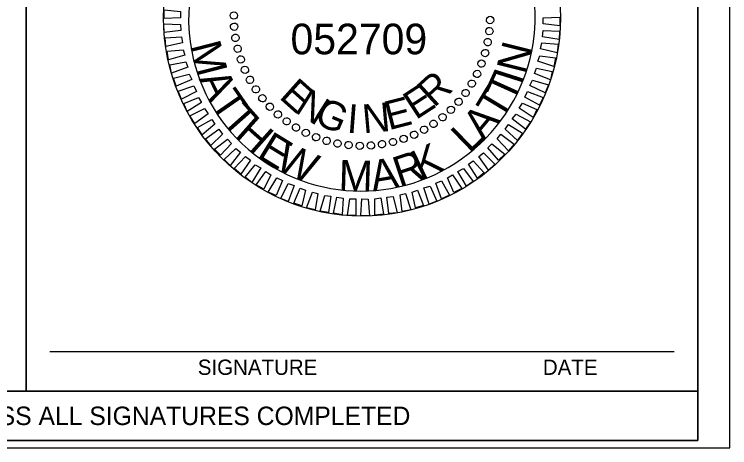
# Model space of a CAD drawing. Extents: x 265553 to 275568, y 168312 to 173522.
# Drawn here: x 273933.1 to 274213.2, y 172139.7 to 172309.6 of the extents above; entities that cross this region are included whole.
import ezdxf

# ---------------------------------------------------------------- set-up
doc = ezdxf.new("R2010")
doc.units = 0
for name, color, linetype in [('Geotech Sheets and Borders Cell', 7, 'Continuous'), ('Scratch_Level_0', 7, 'Continuous'), ('Scratch_Level_6', 7, 'Continuous'), ('Sheet Plot Border Inside CELL', 7, 'Continuous'), ('Sheet Professional Seal CELL', 7, 'Continuous'), ('Sheet Sticker Exception Certification CELL', 7, 'Continuous')]:
    doc.layers.add(name, color=color, linetype=linetype)

msp = doc.modelspace()

# ---------------------------------------------------------------- linework, layer by layer
at = {"layer": 'Geotech Sheets and Borders Cell'}
msp.add_line((274191.42, 172177.29), (273947, 172177.29), dxfattribs=at)
for points in [[(272700.69, 173192.58), (274200.69, 173192.58), (274200.69, 172142.58), (272700.69, 172142.58)], [(273674.76, 172409.27), (273937.73, 172409.27), (273937.73, 172161.9), (273674.76, 172161.9)], [(273937.73, 172409.27), (274200.69, 172409.27), (274200.69, 172161.9), (273937.73, 172161.9)]]:
    msp.add_lwpolyline(points, close=True, dxfattribs=at)
msp.add_lwpolyline([(274200.69, 172409.27), (273674.76, 172409.27), (273674.76, 172142.58), (274200.69, 172142.58), (274200.69, 172410.73)], dxfattribs=at)
at = {"layer": 'Scratch_Level_0'}
msp.add_ellipse((274069.21, 172308.22), major_axis=(45.09, 51.04), ratio=0.993455, start_param=1.731198, end_param=5.992706, dxfattribs=at)
at = {"layer": 'Scratch_Level_6'}
msp.add_circle((274069.21, 172308.22), 77.7, dxfattribs=at)
at = {"layer": 'Sheet Plot Border Inside CELL'}
msp.add_lwpolyline([(272545.53, 172139.74), (274213.19, 172139.74), (274213.19, 173195.41), (272545.53, 173195.41)], close=True, dxfattribs=at)
at = {"layer": 'Sheet Professional Seal CELL'}
for p, q in [((274019.01, 172309.12), (274019.01, 172309.12)), ((274119.41, 172307.32), (274119.41, 172307.32)), ((274019.11, 172304.72), (274019.11, 172304.72)), ((274119.11, 172302.92), (274119.11, 172302.92)), ((274019.71, 172300.42), (274019.71, 172300.42)), ((274118.41, 172298.62), (274118.41, 172298.62)), ((274020.51, 172296.02), (274020.51, 172296.02)), ((274117.51, 172294.42), (274117.51, 172294.42)), ((274021.71, 172291.82), (274021.71, 172291.82)), ((274116.11, 172290.22), (274116.11, 172290.22)), ((274023.31, 172287.82), (274023.31, 172287.82)), ((274114.31, 172286.22), (274114.31, 172286.22)), ((274025.31, 172283.92), (274025.31, 172283.92)), ((274112.31, 172282.32), (274112.31, 172282.32)), ((274027.61, 172280.12), (274027.61, 172280.12)), ((274109.81, 172278.72), (274109.81, 172278.72)), ((274030.11, 172276.62), (274030.11, 172276.62)), ((274107.11, 172275.22), (274107.11, 172275.22)), ((274033.11, 172273.32), (274033.11, 172273.32)), ((274104.11, 172272.12), (274104.11, 172272.12)), ((274036.21, 172270.32), (274036.21, 172270.32)), ((274039.71, 172267.62), (274039.71, 172267.62)), ((274097.31, 172266.62), (274097.31, 172266.62)), ((274100.81, 172269.12), (274100.81, 172269.12)), ((274043.31, 172265.12), (274043.31, 172265.12)), ((274093.51, 172264.32), (274093.51, 172264.32)), ((274047.21, 172263.12), (274047.21, 172263.12)), ((274051.21, 172261.32), (274051.21, 172261.32)), ((274089.61, 172262.32), (274089.61, 172262.32)), ((274055.41, 172259.92), (274055.41, 172259.92)), ((274059.61, 172259.02), (274059.61, 172259.02)), ((274063.91, 172258.32), (274063.91, 172258.32)), ((274068.31, 172258.02), (274068.31, 172258.02)), ((274072.71, 172258.12), (274072.71, 172258.12)), ((274077.01, 172258.72), (274077.01, 172258.72)), ((274081.41, 172259.52), (274081.41, 172259.52)), ((274085.61, 172260.72), (274085.61, 172260.72))]:
    msp.add_line(p, q, dxfattribs=at)
for points in [[(273998.21, 172308.22), (273991.71, 172307.92), (273991.71, 172311.32), (273998.21, 172310.62)], [(274140.21, 172308.22), (274146.71, 172308.52), (274146.71, 172305.12), (274140.21, 172305.82)], [(273998.31, 172303.22), (273991.81, 172302.42), (273991.61, 172305.82), (273998.11, 172305.62)], [(274140.11, 172303.22), (274146.61, 172303.02), (274146.41, 172299.72), (274139.91, 172300.82)], [(273998.91, 172298.42), (273992.41, 172297.02), (273992.11, 172300.42), (273998.51, 172300.82)], [(274139.61, 172298.42), (274146.01, 172297.82), (274145.61, 172294.42), (274139.11, 172296.02)], [(273999.81, 172293.62), (273993.51, 172291.72), (273992.91, 172295.12), (273999.21, 172295.72)], [(274138.81, 172293.32), (274145.01, 172292.52), (274144.31, 172289.12), (274138.01, 172291.22)], [(274001.01, 172288.82), (273994.61, 172286.52), (273994.01, 172289.82), (274000.31, 172290.92)], [(274002.61, 172284.02), (273996.51, 172281.42), (273995.41, 172284.52), (274001.61, 172286.12)], [(274137.51, 172288.52), (274143.71, 172287.22), (274143.01, 172283.92), (274136.71, 172286.42)], [(274136.01, 172283.72), (274142.21, 172281.92), (274140.91, 172278.82), (274134.91, 172281.62)], [(274004.41, 172279.32), (273998.51, 172276.32), (273997.21, 172279.52), (274003.41, 172281.52)], [(274134.01, 172279.32), (274140.21, 172277.02), (274138.71, 172273.92), (274133.01, 172277.12)], [(274006.41, 172275.02), (274000.81, 172271.52), (273999.51, 172274.62), (274005.21, 172276.92)], [(274009.01, 172270.62), (274003.71, 172266.82), (274001.81, 172269.82), (274007.61, 172272.62)], [(274132.01, 172274.72), (274137.71, 172272.22), (274136.21, 172269.12), (274130.81, 172272.82)], [(274129.61, 172270.42), (274135.21, 172267.42), (274133.21, 172264.62), (274128.01, 172268.62)], [(274011.61, 172266.52), (274006.71, 172262.32), (274004.81, 172265.22), (274010.41, 172268.42)], [(274126.61, 172266.42), (274132.01, 172263.02), (274130.11, 172260.12), (274125.31, 172264.52)], [(274014.61, 172262.62), (274010.01, 172258.12), (274007.91, 172260.82), (274013.21, 172264.62)], [(274123.61, 172262.62), (274128.81, 172258.72), (274126.61, 172256.12), (274122.21, 172260.82)], [(274018.11, 172259.02), (274013.81, 172254.32), (274011.41, 172256.72), (274016.61, 172260.62)], [(274120.11, 172258.82), (274125.21, 172254.72), (274122.71, 172252.42), (274118.51, 172257.22)], [(274021.71, 172255.52), (274017.61, 172250.32), (274015.21, 172252.72), (274019.81, 172257.02)], [(274116.81, 172255.32), (274121.21, 172250.92), (274118.81, 172248.52), (274114.91, 172253.92)], [(274025.51, 172252.42), (274021.81, 172246.92), (274019.21, 172249.12), (274023.61, 172253.82)], [(274029.61, 172249.42), (274026.11, 172243.62), (274023.51, 172245.72), (274027.41, 172250.62)], [(274112.81, 172252.22), (274117.11, 172247.42), (274114.41, 172245.32), (274110.91, 172250.92)], [(274033.51, 172246.72), (274030.81, 172241.02), (274027.81, 172242.72), (274031.61, 172247.92)], [(274109.01, 172249.22), (274112.71, 172244.12), (274110.11, 172242.22), (274106.81, 172248.02)], [(274038.11, 172244.42), (274035.61, 172238.52), (274032.51, 172239.92), (274035.91, 172245.52)], [(274100.31, 172244.32), (274103.51, 172238.72), (274100.41, 172237.32), (274098.11, 172243.42)], [(274104.61, 172246.72), (274108.31, 172241.32), (274105.21, 172239.72), (274102.71, 172245.52)], [(274042.61, 172242.52), (274040.31, 172236.22), (274037.51, 172237.42), (274040.31, 172243.22)], [(274047.11, 172240.72), (274045.61, 172234.52), (274042.51, 172235.52), (274045.01, 172241.42)], [(274095.91, 172242.22), (274098.51, 172236.42), (274095.51, 172235.22), (274093.41, 172241.62)], [(274051.91, 172239.42), (274050.91, 172232.92), (274047.51, 172233.72), (274049.81, 172239.92)], [(274057.01, 172238.32), (274056.11, 172231.92), (274052.81, 172232.42), (274054.61, 172238.62)], [(274086.21, 172239.32), (274088.31, 172233.02), (274084.91, 172232.32), (274084.11, 172238.82)], [(274091.01, 172240.62), (274093.31, 172234.62), (274090.21, 172233.72), (274088.91, 172239.92)], [(274061.81, 172237.52), (274061.41, 172231.02), (274058.11, 172231.62), (274059.41, 172237.92)], [(274066.81, 172237.22), (274066.81, 172230.72), (274063.51, 172230.82), (274064.41, 172237.32)], [(274071.61, 172237.12), (274072.11, 172230.62), (274068.81, 172230.72), (274069.21, 172237.22)], [(274076.61, 172237.62), (274077.71, 172231.22), (274074.31, 172230.82), (274074.21, 172237.32)], [(274081.41, 172238.22), (274083.01, 172231.82), (274079.71, 172231.52), (274079.01, 172237.92)]]:
    msp.add_lwpolyline(points, close=True, dxfattribs=at)
for centre, major_axis in [((274019.06, 172309.1), (-1.44, 0.03)), ((274119.36, 172307.35), (1.44, -0.03)), ((274019.17, 172304.72), (-1.44, -0.1)), ((274119.1, 172302.98), (1.43, -0.15)), ((274019.67, 172300.38), (-1.42, -0.23)), ((274118.45, 172298.65), (1.41, -0.27)), ((274020.54, 172296.09), (-1.4, -0.35)), ((274117.43, 172294.4), (1.38, -0.4)), ((274021.78, 172291.89), (-1.36, -0.47)), ((274116.04, 172290.25), (1.34, -0.52)), ((274023.39, 172287.82), (-1.32, -0.59)), ((274114.29, 172286.23), (1.29, -0.63)), ((274025.34, 172283.9), (-1.26, -0.7)), ((274112.21, 172282.39), (1.23, -0.74)), ((274027.63, 172280.17), (-1.19, -0.81)), ((274109.79, 172278.74), (1.16, -0.85)), ((274030.23, 172276.66), (-1.12, -0.91)), ((274033.13, 172273.38), (-1.04, -1)), ((274107.07, 172275.31), (1.09, -0.94)), ((274036.3, 172270.37), (-0.94, -1.09)), ((274104.05, 172272.14), (1, -1.04)), ((274039.73, 172267.64), (-0.85, -1.16)), ((274100.78, 172269.24), (0.91, -1.12)), ((274043.38, 172265.23), (-0.74, -1.23)), ((274097.26, 172266.64), (0.81, -1.19)), ((274047.22, 172263.14), (-0.63, -1.29)), ((274089.61, 172262.4), (0.59, -1.32)), ((274093.53, 172264.35), (0.7, -1.26)), ((274051.23, 172261.39), (-0.52, -1.34)), ((274055.38, 172260), (-0.4, -1.38)), ((274081.35, 172259.55), (0.35, -1.4)), ((274085.54, 172260.79), (0.47, -1.36)), ((274059.64, 172258.98), (-0.27, -1.41)), ((274063.97, 172258.34), (-0.15, -1.43)), ((274068.34, 172258.07), (-0.03, -1.44)), ((274072.71, 172258.18), (0.1, -1.44)), ((274077.06, 172258.68), (0.23, -1.42))]:
    msp.add_ellipse(centre, major_axis=major_axis, ratio=0.999708, dxfattribs=at)
at = {"layer": 'Sheet Sticker Exception Certification CELL'}
for p, q in [((273674.76, 172161.9), (274200.69, 172161.9)), ((274200.69, 172161.9), (274200.69, 172142.58)), ((273674.76, 172142.58), (274200.69, 172142.58))]:
    msp.add_line(p, q, dxfattribs=at)

# ---------------------------------------------------------------- texts
at = {"layer": 'Geotech Sheets and Borders Cell'}
for s, p in [('SIGNATURE', (274004.93, 172168.28)), ('DATE', (274140.04, 172168.28))]:
    msp.add_text(s, height=6, dxfattribs=at).set_placement(p)
at = {"layer": 'Sheet Professional Seal CELL'}
msp.add_text('052709', height=11.996, dxfattribs=at).set_placement((274041.23, 172293.91))
for s, height, rotation, p in [('M', 12, 284.4427, (274001.81, 172297.44)), ('N', 12, 76.0485, (274133.42, 172285.66)), ('R', 11.28, 42.4814, (274097.41, 172272.72)), ('T', 12, 65.5939, (274128.16, 172274.3)), ('I', 12, 72.2964, (274131.77, 172281.48)), ('A', 12, 295.9532, (274005.21, 172284.26)), ('E', 11.28, 318.2769, (274036.41, 172276.92)), ('T', 12, 304.8011, (274009.56, 172274.77)), ('N', 11.28, 327.634, (274042.41, 172271.52)), ('E', 11.28, 33.1241, (274090.31, 172268.02)), ('T', 12, 58.9001, (274123.73, 172267.6)), ('T', 12, 311.616, (274013.87, 172267.99)), ('G', 11.28, 336.9902, (274050.01, 172267.02)), ('N', 11.28, 5.0564, (274069.81, 172262.92)), ('E', 11.28, 14.4118, (274079.71, 172264.12)), ('I', 11.28, 355.7012, (274063.11, 172263.22)), ('A', 12, 50.2057, (274116.87, 172259.73)), ('H', 12, 318.4346, (274018.95, 172261.77)), ('L', 12, 44.0359, (274111.32, 172254.82)), ('E', 12, 328.4447, (274027.67, 172253.83)), ('W', 12, 335.5662, (274034.66, 172249.16)), ('K', 12, 25.8388, (274092.34, 172244.18)), ('R', 12, 18.455, (274083.86, 172241.67)), ('M', 12, 358.2604, (274059.93, 172240.55)), ('A', 12, 9.7075, (274073.53, 172240.14))]:
    msp.add_text(s, height=height, rotation=rotation, dxfattribs=at).set_placement(p)
at = {"layer": 'Sheet Sticker Exception Certification CELL'}
msp.add_text('DOCUMENT NOT CONSIDERED FINAL UNLESS ALL SIGNATURES COMPLETED', height=7.2302, dxfattribs=at).set_placement((273722.32, 172148.62))

doc.saveas('drawing.dxf')
